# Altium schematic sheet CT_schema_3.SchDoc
size 293 x 156 mm
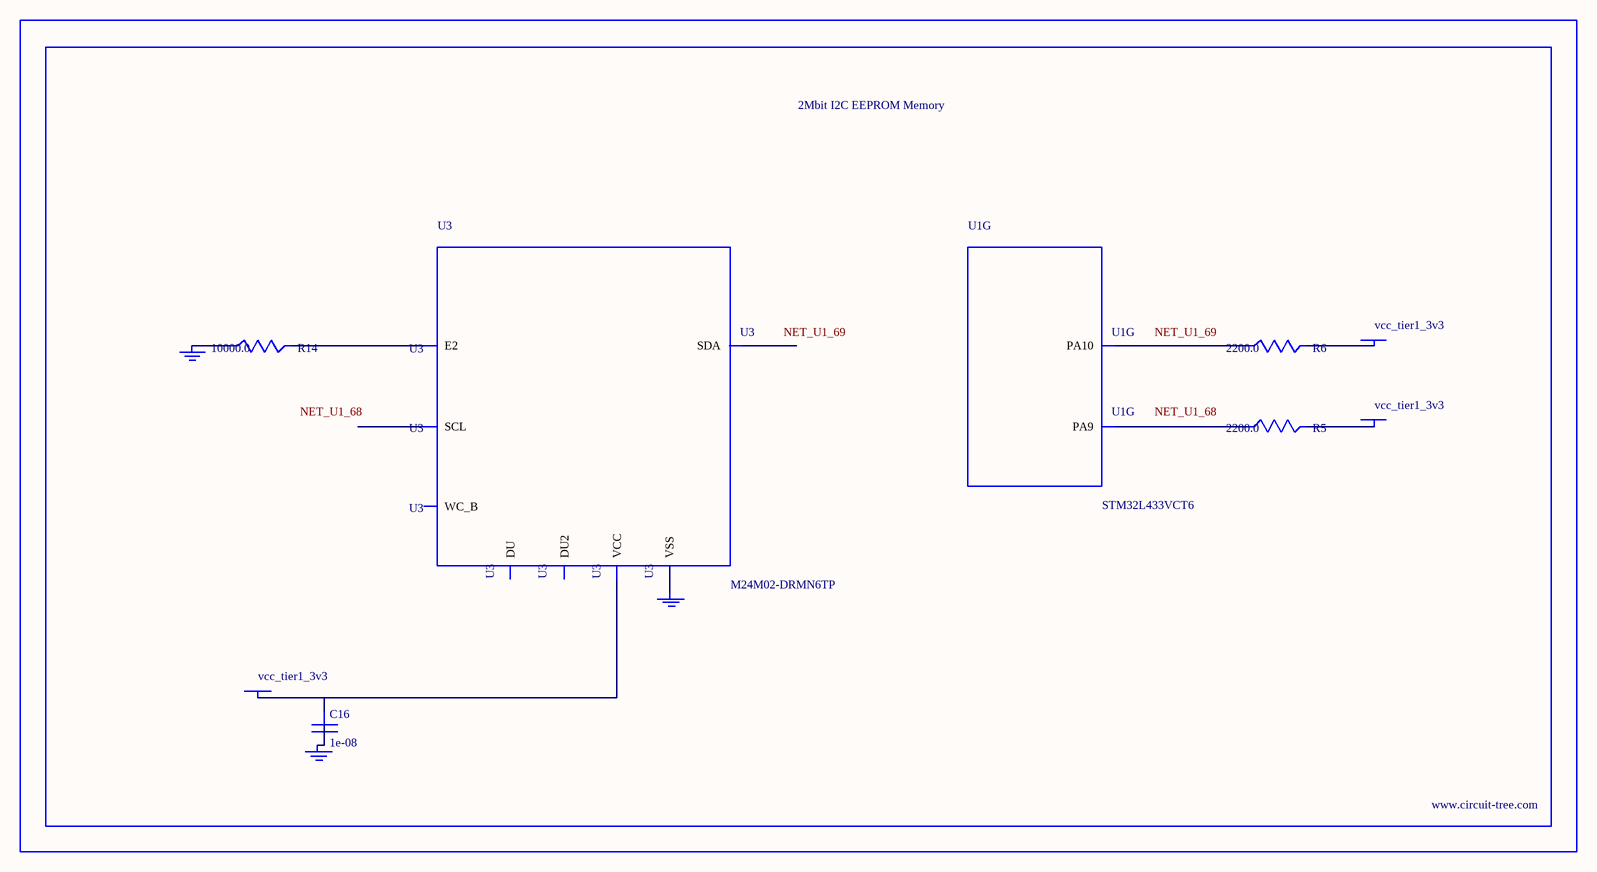
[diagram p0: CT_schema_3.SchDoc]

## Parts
BORDER2  (no value)
C16  1e-08  [C0402]
GND_INSTANCE_2_0  (no value)
GND_INSTANCE_2_1  (no value)
GND_INSTANCE_2_2  (no value)
POWER_INSTANCE_2_0  vcc_tier1_3v3
POWER_INSTANCE_2_1  vcc_tier1_3v3
POWER_INSTANCE_2_2  vcc_tier1_3v3
R5  2200.0  [R0603]
R6  2200.0  [R0603]
R14  10000.0  [R0603]
U1  STM32L433VCT6  [LQFP100]  (part G of 9)
U3  M24M02-DRMN6TP  [SOIC-8]

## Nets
NetC16_1: C16.1 POWER_INSTANCE_2_0.0(PWR) U3.8(VCC)
NetC16_2: C16.2 GND_INSTANCE_2_1.0(GND)
NetGND_INSTANCE_2_0_0: GND_INSTANCE_2_0.0(GND) R14.1
NetGND_INSTANCE_2_2_0: GND_INSTANCE_2_2.0(GND) U3.4(VSS)
NetPOWER_INSTANCE_2_1_0: POWER_INSTANCE_2_1.0(PWR) R5.2
NetPOWER_INSTANCE_2_2_0: POWER_INSTANCE_2_2.0(PWR) R6.2
NetR5_1: R5.1 U1.68(PA9)
NetR6_1: R6.1 U1.69(PA10)
NetR14_2: R14.2 U3.3(E2)

Not connected (* = marked no-connect by the designer): U3 1(DU) 2(DU2) 5(SDA) 6(SCL) 7(WC_B)

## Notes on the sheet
- Labels drawn without touching a wire or pin: NET_U1_68, NET_U1_69

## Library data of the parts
BORDER2 = BORDER_PAGE2
C16 = C0402C103K3RAC
GND_INSTANCE_2_0-GND_INSTANCE_2_2 = GND
POWER_INSTANCE_2_0-POWER_INSTANCE_2_2 = PWR
R5 R6 = RC0603JR-072K2L
R14 = RC0603JR-0710KL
